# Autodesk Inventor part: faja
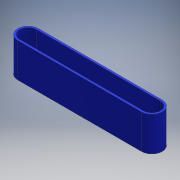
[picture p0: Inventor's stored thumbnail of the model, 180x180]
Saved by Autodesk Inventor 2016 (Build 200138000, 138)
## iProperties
Created: 2016-06
Part Number: faja
Material: Genérico
Document SubType Name: Modeling
Designer: adm
Density: 1 g/cm^3
Appearance: Valor por defecto
Author: adm
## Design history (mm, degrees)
sketch "Boceto1"
  geometry: L1 (-180, 15)-(180, 15); L2 (180, -35)-(-180, -35); L3 (180, 20)-(-180, 20); L4 (-180, -40)-(180, -40); A1 r 25 centre (-180, -10) between (-180, 15) and (-180, -35); A2 r 25 centre (180, -10) between (180, -35) and (180, 15); A3 r 30 centre (-180, -10) between (-180, 20) and (-180, -40); A4 r 30 centre (180, -10) between (180, -40) and (180, 20); 1 further point
  constraints: 8 end point, 8 point on circle, 4 centre point, 3 tangent, 3 other
  dimensions: "d0" = 50 diameter of A1; "d2" = 50 diameter of A2; "d4" = 5 distance between parallel lines of L1 L3
extrude "Extrusión1" new body sketch "Boceto1" distance "d5" = 100; taper "d6" = 0 deg
node "Sólido1"
